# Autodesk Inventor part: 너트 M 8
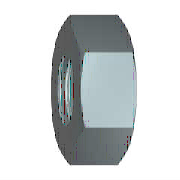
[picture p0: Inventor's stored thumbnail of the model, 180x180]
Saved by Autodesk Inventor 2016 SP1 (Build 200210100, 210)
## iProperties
IsCustomPart: 1
Created: 2012-02
Part Number: 너트 M 8
Material: 강철, 연강
Description: 6각 너트 및 6각 가는 너트
Document SubType Name: Modeling
Standard: KS B 1012
Designer: mduedu
Standards Organization: KS
Language: ko-KR
Size Designation: M 8
Categories: <MemberInstance><Categories><Category DisplayName="조임쇠" InternalName="e4da775c-781d-43d5-af7c-5136215cf5a6" Mnemonic="FSTN"><Category DisplayName="너트" InternalN
Density: 1 g/cm^3
Appearance: 강철
Author: mduedu
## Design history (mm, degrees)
sketch "스케치1"
  geometry: L1 (-7.506, 0)-(-3.753, 6.5); L2 (-3.753, 6.5)-(3.753, 6.5); L3 (3.753, 6.5)-(7.506, 0); L4 (7.506, 0)-(3.753, -6.5); L5 (3.753, -6.5)-(-3.753, -6.5); L6 (-3.753, -6.5)-(-7.506, 0); 2 further points
  constraints: 12 end point, 1 coincident, 1 horizontal, 11 other
  dimensions: "d0" = 15.01111 distance of L3.end L1.start (= 1.1547 x SW)
extrude "본체" new body sketch "스케치1" distance "d1" = 5 (= KOH); taper "d2" = 0 deg
sketch "스케치2"
  geometry: L1 (0, 3.753)-(0, 7.506) reference; L2 (0, 7.506)-(5, 7.506) reference; L3 (5, 3.753)-(5, 7.506) reference; L4 (-1, 0)-(6, 0) reference; L5 (0.581, 7.506)-(0, 6.5); L6 (4.419, 7.506)-(5, 6.5)
  constraints: 4 end point, 4 point on line
  dimensions: "d3" = 30 deg angle of L1 L5 (= ANG1); "d4" = 30 deg angle of L3 L6 (= ANG2); "d5" = 13 diameter of L5.end L4 (= SW0); "d6" = 13 diameter of L6.end L4 (= SW01)
revolve "모따기1" sketch "스케치2" stored, may be unused: angle "d7" = 90 deg
sketch "스케치3"
  geometry: A1 r 6.5 centre (0, 0) between (-3.25, -5.629) and (3.25, -5.629) reference; 1 further point
  constraints: 1 coincident
hole "스레드" sketch "스케치3" at (0, 0) diameter "d25" = 6.647; stored, may be unused: countersink angle "d29" = 82 deg, drill point angle "d31" = 118 deg; dims "d26" = 6, "d27" = 4, "d28" = 2, "d30" = 8
workaxis "Work Axis1"
workplane "Work Plane1"
body "Solid1"
chamfer "모따기2" distance "d8" = 0.67658 (= -0.5 x GD1 + 0.5 x NND); stored, may be unused: angle "d9" = 30 deg, second distance "d40" = 0.67658 (= -0.5 x GD1 + 0.5 x NND)
chamfer "모따기3" distance "d10" = 0.67658 (= -0.5 x GD1 + 0.5 x NND); stored, may be unused: angle "d11" = 30 deg, second distance "d41" = 0.67658 (= -0.5 x GD1 + 0.5 x NND)
other parameters: "ANG1" = 30 deg [user parameter; used in 1 equation term], "ANG2" = 30 deg [user parameter; used in 1 equation term], "NND" = 8 [user parameter; used in 4 equation terms], "KOH" = 5 [user parameter; used in 1 equation term], "SW" = 13 [user parameter; used in 4 equation terms], "SW0" = 13 (= SW) [user parameter; used in 1 equation term], "SW01" = 13 (= SW) [user parameter; used in 1 equation term], "GD1" = 6.64684 (computed from THREADDIA, PTC, TOA) [user parameter; used in 4 equation terms], "d13" = 0, "d14" = 0, "d39" = 0, "d42" = 0, "GUL" = 0.67658 (= 0.541266 x PTC) [user parameter], "TPU" = 8 (computed from PTC) [user parameter], "THREADDIA" = 8 [user parameter; used in 1 equation term], "TOA" = 30 deg [user parameter; used in 1 equation term], "PTC" = 1.25 [user parameter; used in 4 equation terms], "E0" = 15.015 (= 1.155 x SW) [user parameter], "GAL" = 0.67658 (= 0.541266 x PTC) [user parameter]
